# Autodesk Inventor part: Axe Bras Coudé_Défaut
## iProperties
Shininess: 64.0
Length Units: 11269
Angle Units: 11279
Time Units: 11290
Mass Units: 11283
Length Display Precision: 3
Angle Display Precision: 2
Compacted: True
Part Number: Axe Bras Coudé_Défaut
Document SubType Name: Modeling
Created: 2006-11
Material: Par défaut
Designer: profs_sti
Density: 0.0
Volumn: 0.0
Area: 0.0
PropertySet Name: Model Information
Control State: 0
Master: False
Checked Out: False
Author: profs_sti
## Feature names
1. Base1
